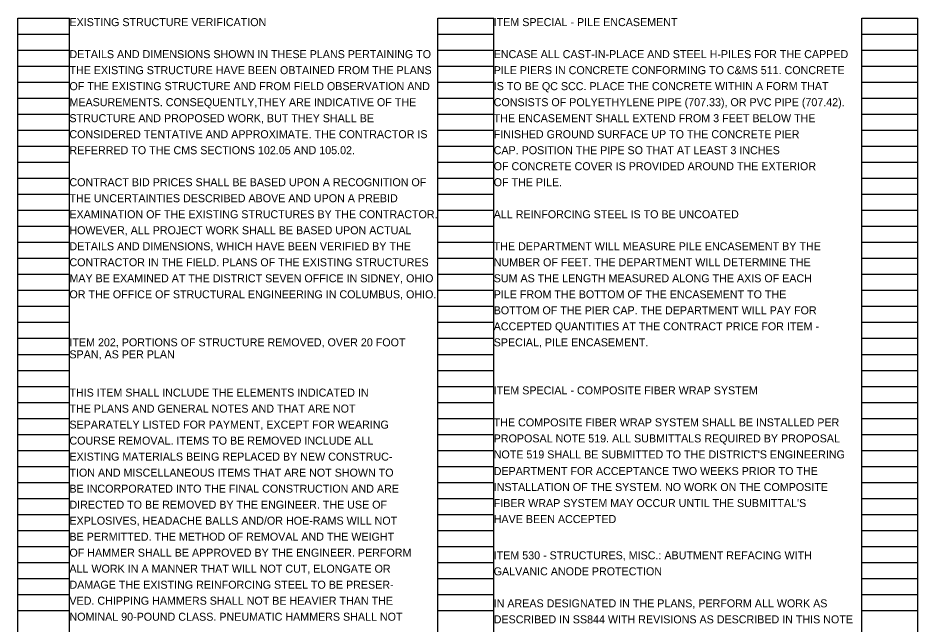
# Model space of a CAD drawing. Extents: x 0 to 66.4, y 0 to 28.8.
# Drawn here: x 35.91 to 51.65, y 10.53 to 21.14 of the extents above; entities that cross this region are included whole.
import ezdxf

# ---------------------------------------------------------------- set-up
doc = ezdxf.new("R2010")
doc.units = 0
doc.layers.add('SH_Data', color=7, linetype='Continuous')
doc.layers.add('SH_Text', color=7, linetype='Continuous')

msp = doc.modelspace()

# ---------------------------------------------------------------- linework, layer by layer
at = {"layer": 'SH_Data'}
for p, q in [((35.914, 0.98), (35.914, 21.14)), ((35.914, 21.14), (36.814, 21.14)), ((35.914, 0.98), (35.914, 21.14)), ((35.914, 21.14), (36.814, 21.14)), ((36.814, 0.98), (36.814, 21.14)), ((36.814, 0.98), (36.814, 21.14)), ((43.254, 0.98), (43.254, 21.14)), ((43.254, 21.14), (44.234, 21.14)), ((43.254, 0.98), (43.254, 21.14)), ((43.254, 21.14), (44.234, 21.14)), ((44.234, 0.98), (44.234, 21.14)), ((44.234, 0.98), (44.234, 21.14)), ((50.674, 0.98), (50.674, 21.14)), ((50.674, 21.14), (51.654, 21.14)), ((50.674, 0.98), (50.674, 21.14)), ((50.674, 21.14), (51.654, 21.14)), ((51.654, 0.98), (51.654, 21.14)), ((51.654, 0.98), (51.654, 21.14)), ((35.914, 20.86), (36.814, 20.86)), ((35.914, 20.86), (36.814, 20.86)), ((43.254, 20.86), (44.234, 20.86)), ((43.254, 20.86), (44.234, 20.86)), ((50.674, 20.86), (51.654, 20.86)), ((50.674, 20.86), (51.654, 20.86)), ((35.914, 20.58), (36.814, 20.58)), ((35.914, 20.58), (36.814, 20.58)), ((43.254, 20.58), (44.234, 20.58)), ((43.254, 20.58), (44.234, 20.58)), ((50.674, 20.58), (51.654, 20.58)), ((50.674, 20.58), (51.654, 20.58)), ((35.914, 20.3), (36.814, 20.3)), ((35.914, 20.3), (36.814, 20.3)), ((43.254, 20.3), (44.234, 20.3)), ((43.254, 20.3), (44.234, 20.3)), ((50.674, 20.3), (51.654, 20.3)), ((50.674, 20.3), (51.654, 20.3)), ((35.914, 20.02), (36.814, 20.02)), ((35.914, 20.02), (36.814, 20.02)), ((43.254, 20.02), (44.234, 20.02)), ((43.254, 20.02), (44.234, 20.02)), ((50.674, 20.02), (51.654, 20.02)), ((50.674, 20.02), (51.654, 20.02)), ((35.914, 19.74), (36.814, 19.74)), ((35.914, 19.74), (36.814, 19.74)), ((43.254, 19.74), (44.234, 19.74)), ((43.254, 19.74), (44.234, 19.74)), ((50.674, 19.74), (51.654, 19.74)), ((50.674, 19.74), (51.654, 19.74)), ((35.914, 19.46), (36.814, 19.46)), ((35.914, 19.46), (36.814, 19.46)), ((43.254, 19.46), (44.234, 19.46)), ((43.254, 19.46), (44.234, 19.46)), ((50.674, 19.46), (51.654, 19.46)), ((50.674, 19.46), (51.654, 19.46)), ((35.914, 19.18), (36.814, 19.18)), ((35.914, 19.18), (36.814, 19.18)), ((43.254, 19.18), (44.234, 19.18)), ((43.254, 19.18), (44.234, 19.18)), ((50.674, 19.18), (51.654, 19.18)), ((50.674, 19.18), (51.654, 19.18)), ((35.914, 18.9), (36.814, 18.9)), ((35.914, 18.9), (36.814, 18.9)), ((43.254, 18.9), (44.234, 18.9)), ((43.254, 18.9), (44.234, 18.9)), ((50.674, 18.9), (51.654, 18.9)), ((50.674, 18.9), (51.654, 18.9)), ((35.914, 18.62), (36.814, 18.62)), ((35.914, 18.62), (36.814, 18.62)), ((43.254, 18.62), (44.234, 18.62)), ((43.254, 18.62), (44.234, 18.62)), ((50.674, 18.62), (51.654, 18.62)), ((50.674, 18.62), (51.654, 18.62)), ((35.914, 18.34), (36.814, 18.34)), ((35.914, 18.34), (36.814, 18.34)), ((43.254, 18.34), (44.234, 18.34)), ((43.254, 18.34), (44.234, 18.34)), ((50.674, 18.34), (51.654, 18.34)), ((50.674, 18.34), (51.654, 18.34)), ((35.914, 18.06), (36.814, 18.06)), ((35.914, 18.06), (36.814, 18.06)), ((43.254, 18.06), (44.234, 18.06)), ((43.254, 18.06), (44.234, 18.06)), ((50.674, 18.06), (51.654, 18.06)), ((50.674, 18.06), (51.654, 18.06)), ((35.914, 17.78), (36.814, 17.78)), ((35.914, 17.78), (36.814, 17.78)), ((43.254, 17.78), (44.234, 17.78)), ((43.254, 17.78), (44.234, 17.78)), ((50.674, 17.78), (51.654, 17.78)), ((50.674, 17.78), (51.654, 17.78)), ((35.914, 17.5), (36.814, 17.5)), ((35.914, 17.5), (36.814, 17.5)), ((43.254, 17.5), (44.234, 17.5)), ((43.254, 17.5), (44.234, 17.5)), ((50.674, 17.5), (51.654, 17.5)), ((50.674, 17.5), (51.654, 17.5)), ((35.914, 17.22), (36.814, 17.22)), ((35.914, 17.22), (36.814, 17.22)), ((43.254, 17.22), (44.234, 17.22)), ((43.254, 17.22), (44.234, 17.22)), ((50.674, 17.22), (51.654, 17.22)), ((50.674, 17.22), (51.654, 17.22)), ((35.914, 16.94), (36.814, 16.94)), ((35.914, 16.94), (36.814, 16.94)), ((43.254, 16.94), (44.234, 16.94)), ((43.254, 16.94), (44.234, 16.94)), ((50.674, 16.94), (51.654, 16.94)), ((50.674, 16.94), (51.654, 16.94)), ((35.914, 16.66), (36.814, 16.66)), ((35.914, 16.66), (36.814, 16.66)), ((43.254, 16.66), (44.234, 16.66)), ((43.254, 16.66), (44.234, 16.66)), ((50.674, 16.66), (51.654, 16.66)), ((50.674, 16.66), (51.654, 16.66)), ((35.914, 16.38), (36.814, 16.38)), ((35.914, 16.38), (36.814, 16.38)), ((43.254, 16.38), (44.234, 16.38)), ((43.254, 16.38), (44.234, 16.38)), ((50.674, 16.38), (51.654, 16.38)), ((50.674, 16.38), (51.654, 16.38)), ((35.914, 16.1), (36.814, 16.1)), ((35.914, 16.1), (36.814, 16.1)), ((43.254, 16.1), (44.234, 16.1)), ((43.254, 16.1), (44.234, 16.1)), ((50.674, 16.1), (51.654, 16.1)), ((50.674, 16.1), (51.654, 16.1)), ((35.914, 15.82), (36.814, 15.82)), ((35.914, 15.82), (36.814, 15.82)), ((43.254, 15.82), (44.234, 15.82)), ((43.254, 15.82), (44.234, 15.82)), ((50.674, 15.82), (51.654, 15.82)), ((50.674, 15.82), (51.654, 15.82)), ((35.914, 15.54), (36.814, 15.54)), ((35.914, 15.54), (36.814, 15.54)), ((43.254, 15.54), (44.234, 15.54)), ((43.254, 15.54), (44.234, 15.54)), ((50.674, 15.54), (51.654, 15.54)), ((50.674, 15.54), (51.654, 15.54)), ((35.914, 15.26), (36.814, 15.26)), ((35.914, 15.26), (36.814, 15.26)), ((43.254, 15.26), (44.234, 15.26)), ((43.254, 15.26), (44.234, 15.26)), ((50.674, 15.26), (51.654, 15.26)), ((50.674, 15.26), (51.654, 15.26)), ((35.914, 14.98), (36.814, 14.98)), ((35.914, 14.98), (36.814, 14.98)), ((43.254, 14.98), (44.234, 14.98)), ((43.254, 14.98), (44.234, 14.98)), ((50.674, 14.98), (51.654, 14.98)), ((50.674, 14.98), (51.654, 14.98)), ((35.914, 14.7), (36.814, 14.7)), ((35.914, 14.7), (36.814, 14.7)), ((43.254, 14.7), (44.234, 14.7)), ((43.254, 14.7), (44.234, 14.7)), ((50.674, 14.7), (51.654, 14.7)), ((50.674, 14.7), (51.654, 14.7)), ((35.914, 14.42), (36.814, 14.42)), ((35.914, 14.42), (36.814, 14.42)), ((43.254, 14.42), (44.234, 14.42)), ((43.254, 14.42), (44.234, 14.42)), ((50.674, 14.42), (51.654, 14.42)), ((50.674, 14.42), (51.654, 14.42)), ((35.914, 14.14), (36.814, 14.14)), ((35.914, 14.14), (36.814, 14.14)), ((43.254, 14.14), (44.234, 14.14)), ((43.254, 14.14), (44.234, 14.14)), ((50.674, 14.14), (51.654, 14.14)), ((50.674, 14.14), (51.654, 14.14)), ((35.914, 13.86), (36.814, 13.86)), ((35.914, 13.86), (36.814, 13.86)), ((43.254, 13.86), (44.234, 13.86)), ((43.254, 13.86), (44.234, 13.86)), ((50.674, 13.86), (51.654, 13.86)), ((50.674, 13.86), (51.654, 13.86)), ((35.914, 13.58), (36.814, 13.58)), ((35.914, 13.58), (36.814, 13.58)), ((43.254, 13.58), (44.234, 13.58)), ((43.254, 13.58), (44.234, 13.58)), ((50.674, 13.58), (51.654, 13.58)), ((50.674, 13.58), (51.654, 13.58)), ((35.914, 13.3), (36.814, 13.3)), ((35.914, 13.3), (36.814, 13.3)), ((43.254, 13.3), (44.234, 13.3)), ((43.254, 13.3), (44.234, 13.3)), ((50.674, 13.3), (51.654, 13.3)), ((50.674, 13.3), (51.654, 13.3)), ((35.914, 13.02), (36.814, 13.02)), ((35.914, 13.02), (36.814, 13.02)), ((43.254, 13.02), (44.234, 13.02)), ((43.254, 13.02), (44.234, 13.02)), ((50.674, 13.02), (51.654, 13.02)), ((50.674, 13.02), (51.654, 13.02)), ((35.914, 12.74), (36.814, 12.74)), ((35.914, 12.74), (36.814, 12.74)), ((43.254, 12.74), (44.234, 12.74)), ((43.254, 12.74), (44.234, 12.74)), ((50.674, 12.74), (51.654, 12.74)), ((50.674, 12.74), (51.654, 12.74)), ((35.914, 12.46), (36.814, 12.46)), ((35.914, 12.46), (36.814, 12.46)), ((43.254, 12.46), (44.234, 12.46)), ((43.254, 12.46), (44.234, 12.46)), ((50.674, 12.46), (51.654, 12.46)), ((50.674, 12.46), (51.654, 12.46)), ((35.914, 12.18), (36.814, 12.18)), ((35.914, 12.18), (36.814, 12.18)), ((43.254, 12.18), (44.234, 12.18)), ((43.254, 12.18), (44.234, 12.18)), ((50.674, 12.18), (51.654, 12.18)), ((50.674, 12.18), (51.654, 12.18)), ((35.914, 11.9), (36.814, 11.9)), ((35.914, 11.9), (36.814, 11.9)), ((43.254, 11.9), (44.234, 11.9)), ((43.254, 11.9), (44.234, 11.9)), ((50.674, 11.9), (51.654, 11.9)), ((50.674, 11.9), (51.654, 11.9)), ((35.914, 11.62), (36.814, 11.62)), ((35.914, 11.62), (36.814, 11.62)), ((43.254, 11.62), (44.234, 11.62)), ((43.254, 11.62), (44.234, 11.62)), ((50.674, 11.62), (51.654, 11.62)), ((50.674, 11.62), (51.654, 11.62)), ((35.914, 11.34), (36.814, 11.34)), ((35.914, 11.34), (36.814, 11.34)), ((43.254, 11.34), (44.234, 11.34)), ((43.254, 11.34), (44.234, 11.34)), ((50.674, 11.34), (51.654, 11.34)), ((50.674, 11.34), (51.654, 11.34)), ((35.914, 11.06), (36.814, 11.06)), ((35.914, 11.06), (36.814, 11.06)), ((43.254, 11.06), (44.234, 11.06)), ((43.254, 11.06), (44.234, 11.06)), ((50.674, 11.06), (51.654, 11.06)), ((50.674, 11.06), (51.654, 11.06)), ((35.914, 10.78), (36.814, 10.78)), ((35.914, 10.78), (36.814, 10.78)), ((43.254, 10.78), (44.234, 10.78)), ((43.254, 10.78), (44.234, 10.78)), ((50.674, 10.78), (51.654, 10.78)), ((50.674, 10.78), (51.654, 10.78))]:
    msp.add_line(p, q, dxfattribs=at)

# ---------------------------------------------------------------- texts
at = {"layer": 'SH_Text'}
for s, p in [('EXISTING STRUCTURE VERIFICATION', (36.814, 21)), ('ITEM SPECIAL - PILE ENCASEMENT', (44.234, 21)), ('DETAILS AND DIMENSIONS SHOWN IN THESE PLANS PERTAINING TO', (36.814, 20.44)), ('ENCASE ALL CAST-IN-PLACE AND STEEL H-PILES FOR THE CAPPED', (44.234, 20.44)), ('THE EXISTING STRUCTURE HAVE BEEN OBTAINED FROM THE PLANS', (36.814, 20.16)), ('PILE PIERS IN CONCRETE CONFORMING TO C&MS 511. CONCRETE ', (44.234, 20.16)), ('OF THE EXISTING STRUCTURE AND FROM FIELD OBSERVATION AND', (36.814, 19.88)), ('IS TO BE QC SCC. PLACE THE CONCRETE WITHIN A FORM THAT ', (44.234, 19.88)), ('MEASUREMENTS. CONSEQUENTLY,THEY ARE INDICATIVE OF THE', (36.814, 19.6)), ('CONSISTS OF POLYETHYLENE PIPE (707.33), OR PVC PIPE (707.42).', (44.234, 19.6)), ('STRUCTURE AND PROPOSED WORK, BUT THEY SHALL BE', (36.814, 19.32)), ('THE ENCASEMENT SHALL EXTEND FROM 3 FEET BELOW THE', (44.234, 19.32)), ('CONSIDERED TENTATIVE AND APPROXIMATE. THE CONTRACTOR IS', (36.814, 19.04)), ('FINISHED GROUND SURFACE UP TO THE CONCRETE PIER', (44.234, 19.04)), ('REFERRED TO THE CMS SECTIONS 102.05 AND 105.02.', (36.814, 18.76)), ('CAP. POSITION THE PIPE SO THAT AT LEAST 3 INCHES', (44.234, 18.76)), ('OF CONCRETE COVER IS PROVIDED AROUND THE EXTERIOR', (44.234, 18.48)), ('CONTRACT BID PRICES SHALL BE BASED UPON A RECOGNITION OF', (36.814, 18.2)), ('OF THE PILE.', (44.234, 18.2)), ('THE UNCERTAINTIES DESCRIBED ABOVE AND UPON A PREBID', (36.814, 17.92)), ('EXAMINATION OF THE EXISTING STRUCTURES BY THE CONTRACTOR.', (36.814, 17.64)), ('ALL REINFORCING STEEL IS TO BE UNCOATED', (44.234, 17.64)), ('HOWEVER, ALL PROJECT WORK SHALL BE BASED UPON ACTUAL', (36.814, 17.36)), ('DETAILS AND DIMENSIONS, WHICH HAVE BEEN VERIFIED BY THE', (36.814, 17.08)), ('THE DEPARTMENT WILL MEASURE PILE ENCASEMENT BY THE', (44.234, 17.08)), ('CONTRACTOR IN THE FIELD. PLANS OF THE EXISTING STRUCTURES', (36.814, 16.8)), ('NUMBER OF FEET. THE DEPARTMENT WILL DETERMINE THE', (44.234, 16.8)), ('MAY BE EXAMINED AT THE DISTRICT SEVEN OFFICE IN SIDNEY, OHIO', (36.814, 16.52)), ('SUM AS THE LENGTH MEASURED ALONG THE AXIS OF EACH', (44.234, 16.52)), ('OR THE OFFICE OF STRUCTURAL ENGINEERING IN COLUMBUS, OHIO.', (36.814, 16.24)), ('PILE FROM THE BOTTOM OF THE ENCASEMENT TO THE', (44.234, 16.24)), ('BOTTOM OF THE PIER CAP. THE DEPARTMENT WILL PAY FOR', (44.234, 15.96)), ('ACCEPTED QUANTITIES AT THE CONTRACT PRICE FOR ITEM -', (44.234, 15.68)), ('ITEM 202, PORTIONS OF STRUCTURE REMOVED, OVER 20 FOOT ', (36.814, 15.4)), ('SPECIAL, PILE ENCASEMENT.', (44.234, 15.4)), ('SPAN, AS PER PLAN', (36.814, 15.19)), ('THIS ITEM SHALL INCLUDE THE ELEMENTS INDICATED IN', (36.814, 14.521)), ('ITEM SPECIAL - COMPOSITE FIBER WRAP SYSTEM', (44.234, 14.56)), ('THE PLANS AND GENERAL NOTES AND THAT ARE NOT', (36.814, 14.241)), ('SEPARATELY LISTED FOR PAYMENT, EXCEPT FOR WEARING', (36.814, 13.961)), ('THE COMPOSITE FIBER WRAP SYSTEM SHALL BE INSTALLED PER', (44.234, 14)), ('PROPOSAL NOTE 519. ALL SUBMITTALS REQUIRED BY PROPOSAL', (44.234, 13.72)), ('COURSE REMOVAL. ITEMS TO BE REMOVED INCLUDE ALL', (36.814, 13.681)), ('EXISTING MATERIALS BEING REPLACED BY NEW CONSTRUC-', (36.814, 13.401)), ("NOTE 519 SHALL BE SUBMITTED TO THE DISTRICT'S ENGINEERING", (44.234, 13.44)), ('TION AND MISCELLANEOUS ITEMS THAT ARE NOT SHOWN TO', (36.814, 13.121)), ('DEPARTMENT FOR ACCEPTANCE TWO WEEKS PRIOR TO THE', (44.234, 13.149)), ('BE INCORPORATED INTO THE FINAL CONSTRUCTION AND ARE', (36.814, 12.841)), ('INSTALLATION OF THE SYSTEM. NO WORK ON THE COMPOSITE', (44.234, 12.869)), ('DIRECTED TO BE REMOVED BY THE ENGINEER. THE USE OF', (36.814, 12.561)), ("FIBER WRAP SYSTEM MAY OCCUR UNTIL THE SUBMITTAL'S", (44.234, 12.589)), ('HAVE BEEN ACCEPTED', (44.234, 12.309)), ('EXPLOSIVES, HEADACHE BALLS AND/OR HOE-RAMS WILL NOT', (36.814, 12.281)), ('BE PERMITTED. THE METHOD OF REMOVAL AND THE WEIGHT', (36.814, 12.001)), ('OF HAMMER SHALL BE APPROVED BY THE ENGINEER. PERFORM', (36.814, 11.721)), ('ITEM 530 - STRUCTURES, MISC.: ABUTMENT REFACING WITH', (44.234, 11.675)), ('ALL WORK IN A MANNER THAT WILL NOT CUT, ELONGATE OR', (36.814, 11.441)), ('GALVANIC ANODE PROTECTION', (44.234, 11.395)), ('DAMAGE THE EXISTING REINFORCING STEEL TO BE PRESER-', (36.814, 11.161)), ('VED. CHIPPING HAMMERS SHALL NOT BE HEAVIER THAN THE', (36.814, 10.881)), ('IN AREAS DESIGNATED IN THE PLANS, PERFORM ALL WORK AS', (44.234, 10.835)), ('NOMINAL 90-POUND CLASS. PNEUMATIC HAMMERS SHALL NOT', (36.814, 10.601)), ('DESCRIBED IN SS844 WITH REVISIONS AS DESCRIBED IN THIS NOTE', (44.234, 10.555))]:
    msp.add_text(s, height=0.14, dxfattribs=at).set_placement(p)

doc.saveas('drawing.dxf')
